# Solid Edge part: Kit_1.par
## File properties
Author: ahadarics
Last saved by: ahadarics
Revision: 76
Sűrűség: 0,000 kg/m^3
Pontosság: 0,990
Username: ahadarics
Dokumentum tartalom típus: 0
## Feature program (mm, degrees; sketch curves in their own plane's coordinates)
base feature "unnamed BaseFeature 1"
sketch for "unnamed Hole 1" plane through (0, 0, 99) normal (0, 0, 1) x-axis (0, 1, 0)
  hole centre (28.25, 28.25) bore radius 3.3235
hole "unnamed Hole 1" through
sketch for "unnamed Hole 2" plane through (0, 0, 99) normal (0, 0, 1) x-axis (0, 1, 0)
  hole centre (-28.25, 28.25) bore radius 3.3235
hole "unnamed Hole 2" through
sketch for "unnamed Hole 3" plane through (0, 0, 99) normal (0, 0, 1) x-axis (0, 1, 0)
  hole centre (-28.25, -28.25) bore radius 3.3235
hole "unnamed Hole 3" through
sketch for "unnamed Hole 4" plane through (0, 0, 99) normal (0, 0, 1) x-axis (0, 1, 0)
  hole centre (28.25, -28.25) bore radius 3.3235
hole "unnamed Hole 4" through
pattern "unnamed Pattern 1" of "unnamed Hole 1", "unnamed Hole 2", "unnamed Hole 3", "unnamed Hole 4"
sketch for "Furat_5" plane through (-37.5359, -0.0029, 91.4955) normal (-0.999944, 0, 0.01058) x-axis (0, 1, 0)
  hole centre (0.0027, 0.0048) bore radius 4.283
hole "Furat_5" diameter 8.566 finite
thread "unnamed Thread 1"
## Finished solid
Body 1: solid body, 308 faces, 750 edges, 456 vertices.
  Faces by surface: plane 141, cylinder 75, swept 61, cone 20, torus 10, spline 1
  Edges by curve: line 431, circle 154, spline 126, ellipse 30, curve on surface 9
Bounding box of the edges (mm; curved faces can reach further): 77.000 x 77.000 x 13.750, from (-38.5, -38.5, 85.25) to (38.5, 38.5, 99).
Cylindrical faces by radius (mm): R0.2 x48, R0.2008 x2, R0.2009 x2, R0.402 x1, R0.4899 x1, R3.3235 x4, R4.283 x1, R4.9 x4, R5.15 x4, R5.25 x4, R8.27 x1, R8.85 x1, R9 x1, R10.25 x1
Conical faces (half-angle, radius in mm at the cone's reference point): 0.5 deg R12 x4, 0.5 deg R13.5 x2, 7 deg R9.5925 x1, 14 deg R8.135 x1, 14 deg R8.4811 x1, 17 deg R8.135 x1, 23 deg R8.829 x1, 42.5 deg R8.1233 x1, 45 deg R3.6735 x4, 45 deg R9 x1, 84 deg R8.4608 x1, 85 deg R9.9463 x1, 87 deg R8.1765 x1
Toroidal faces (ring radius, tube radius in mm): R4.7 r0.2 x8, R8.8057 r0.2025 x1, R9.2522 r0.2925 x1
Planar faces by outward normal: +x 12, +y 13, +z 19, -x 14, -y 14, -z 1, oblique 68
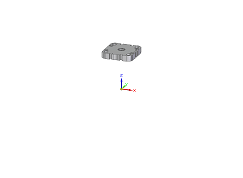
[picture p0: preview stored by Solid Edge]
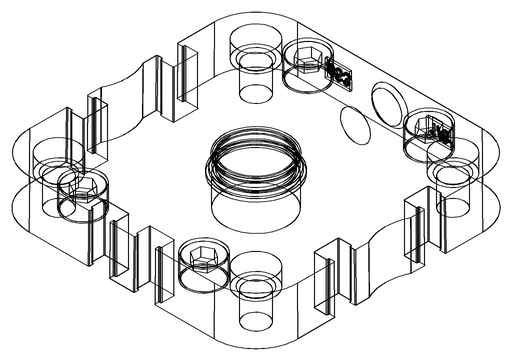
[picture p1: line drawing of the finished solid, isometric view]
